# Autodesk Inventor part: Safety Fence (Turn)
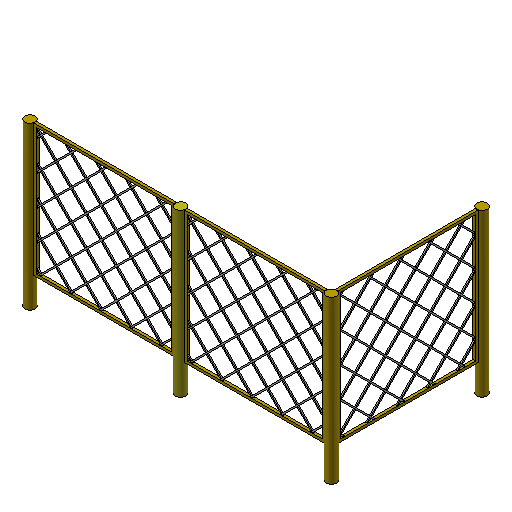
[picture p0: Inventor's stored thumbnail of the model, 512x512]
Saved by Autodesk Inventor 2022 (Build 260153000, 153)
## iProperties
ConnectorClass: SafetyEquipment
family_type: SafetyFence
Created: 2009-11
Part Number: Safety Fence (Turn)
Document SubType Name: Modeling
Designer: Autodesk, Inc.
Density: 1 g/cm^3
Material: 一般
Appearance: 既定
Key Parameters: SectionLength=1321.000 mm;Height=1524.000 mm;BottomHeight=279.000 mm;Number=2.000 ul;Angle=90.00 deg;TurnLength=1321.000 mm;
Author: Autodesk, Inc.
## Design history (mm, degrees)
sketch "Sketch1"
  geometry: L1 (0, -622.5)-(1321, -622.5); L2 (1321, -622.5)-(1321, 622.5); L3 (1321, 622.5)-(0, 622.5); L4 (0, 622.5)-(0, -622.5); L5 (25, -597.5)-(1296, -597.5); L6 (1296, -597.5)-(1296, 597.5); L7 (1296, 597.5)-(25, 597.5); L8 (25, 597.5)-(25, -597.5); 5 further points
  constraints: 16 end point, 4 midpoint, 4 parallel, 2 coincident, 2 horizontal, 2 perpendicular, 1 horizontal alignment, 1 vertical alignment
  dimensions: "d0" = 1245 distance of L3.end L1.start (= Height1); "d2" = 1321 distance of L1.start L1.end (derived); "d53" = 25 distance between parallel lines of L5 L1 (= WidthOfBranch); "d54" = 25 distance between parallel lines of L4 L8 (= WidthOfBranch)
extrude "Extrusion1" new body sketch "Sketch1" stored distance "d4" = 25.4; taper "d5" = 0 deg
sketch "Sketch2"
  geometry: L1 (50.4, 597.5)-(-1448.6, -901.5); L2 (68.361, 597.5)-(-1430.639, -901.5); L3 (-1448.6, -901.5)-(-1430.639, -901.5); L4 (50.4, 597.5)-(68.361, 597.5); L5 (25, 597.5)-(1296, 597.5) reference; L6 (25, -597.5)-(25, 597.5) reference; L7 (1296, 597.5)-(25, 597.5) reference; 2 further points
  constraints: 8 end point, 2 midpoint, 2 parallel, 1 horizontal alignment
  dimensions: "d10" = 12.7 distance between parallel lines of L1 L2; "d20" = 45 deg angle of L5 L1; "d21" = 25.4 distance from line of L6 L1.start; "d51" = 1499 distance between parallel lines of L4 L3 (derived)
extrude "Extrusion2" join sketch "Sketch2" stored distance "d7" = 12.7; taper "d8" = 0 deg
sketch "Sketch3"
  geometry: L1 (-1379.839, 883.539)-(101.2, -597.5); L2 (-1379.839, 901.5)-(119.161, -597.5); L3 (101.2, -597.5)-(119.161, -597.5); L4 (-1379.839, 883.539)-(-1379.839, 901.5); L5 (1296, -597.5)-(25, -597.5) reference; L6 (25, -597.5)-(25, 597.5) reference; 2 further points
  constraints: 8 end point, 2 midpoint, 1 horizontal alignment, 1 parallel, 1 perpendicular
  dimensions: "d13" = 12.7 distance between parallel lines of L1 L2; "d22" = 45 deg angle of L5 L1; "d23" = 76.2 distance of L5.end L1.end; "d24" = 1499 distance from line of L3 L2.start (derived)
extrude "Extrusion3" join sketch "Sketch3" stored distance "d14" = 12.7; taper "d15" = 0 deg
pattern_linear "Rectangular Pattern1" dims "d16" = 113.8 (derived), "d18" = 2845 (derived)
sketch "Sketch4"
  geometry: L1 (25, 597.5)-(25, -597.5) reference; L2 (25, -597.5)-(1296, -597.5) reference; L3 (1296, -597.5)-(1296, 597.5) reference; L4 (1296, 597.5)-(25, 597.5) reference; L5 (1321, -622.5)-(1321, 622.5) reference; L6 (0, -622.5)-(1321, -622.5) reference; L7 (0, 622.5)-(0, -622.5) reference; L8 (1321, 622.5)-(0, 622.5) reference; 1 further point
extrude "Extrusion4" sketch "Sketch4" stored distance "d25" = 127; taper "d26" = 0 deg
pattern_linear "Rectangular Pattern2" dims "d41" = 1420.06 (derived)
sketch "Sketch15"
  geometry: L1 (1194.6, 74.5)-(1176.639, 74.5); L2 (2447.639, 1345.5)-(2465.6, 1345.5); L3 (2465.6, 1345.5)-(1194.6, 74.5); L4 (2447.639, 1345.5)-(1176.639, 74.5); L5 (50.4, 74.5)-(68.361, 74.5); L6 (68.361, 74.5)-(-1202.639, 1345.5); L7 (-1202.639, 1345.5)-(-1220.6, 1345.5); L8 (-1220.6, 1345.5)-(50.4, 74.5); 4 further points
  constraints: 16 end point, 5 parallel, 1 horizontal, 1 horizontal alignment, 1 midpoint
  dimensions: "d87" = 12.7 distance between parallel lines of L3 L4; "d88" = 25.4 distance of point (1220, 74.5) L1.start; "d89" = 1271 horizontal distance of L1.start L2.end (derived); "d90" = 45 deg angle of L1 L4; "d91" = 12.7 distance between parallel lines of L8 L6; "d92" = 25.4 distance of point (25, 74.5) L5.start; "d93" = 1271 horizontal distance of L5.start L7.end (derived); "d94" = 45 deg angle of L6 L5
extrude "Extrusion9" join sketch "Sketch15" stored distance "d97" = 12.7; taper "d98" = 0 deg
sketch "Sketch16"
  geometry: L1 (1370.5, 0)-(49.5, 0) reference; L2 (49.5, 1245)-(1370.5, 1245) reference; L3 (49.5, 0)-(49.5, -3963); L4 (49.5, -3963)-(1370.5, -3963); L5 (1370.5, -3963)-(1370.5, 0); L6 (1370.5, 1245)-(1370.5, 5208); L7 (1370.5, 5208)-(49.5, 5208); L8 (49.5, 5208)-(49.5, 1245)
  constraints: 12 end point, 3 equal length, 3 perpendicular
  dimensions: "d105" = 3963 distance of L4.end L1.start (derived); "d106" = 3963 distance of L2.end L6.end (= d105)
extrude "Extrusion10" cut sketch "Sketch16" distance "d107" = 25.4; taper "d108" = 0 deg
workplane "Work Plane1"
  workaxis "Work Axis1"
workpoint "Work Point1"
  workaxis "Work Axis2"
workaxis "Work Axis3"
workpoint "Work Point2"
workplane "Work Plane5"
  workplane "Work Plane4"
workpoint "Work Point6"
node "Landing Surface"
node "Connector1"
workpoint "Work Point13"
  workaxis "Work Axis9"
  workplane "Work Plane12"
node "Connector2"
workpoint "Work Point14"
node "Insertion Point1"
body "Solid1"
sketch "Sketch9" dims "d42" = 99 (= Diameter)
  geometry: L1 (0, 0)-(0, -25.4) reference; 3 further points
  constraints: 2 horizontal alignment, 1 midpoint, 2 other
extrude "Extrusion5" join sketch "Sketch9" distance "d43" = 1524 (derived); taper "d44" = 0 deg
pattern_linear "Rectangular Pattern3" dims "d114" = 1420.06 (derived)
sketch "Sketch10"
  geometry: L1 (1321, -25.4)-(1321, 0) reference; C1 r 49.5 at (1370.5, -12.7); 1 further point
  constraints: 1 centre point, 1 horizontal alignment, 1 midpoint, 1 tangent
  dimensions: "d45" = 99 diameter of C1 (= Diameter)
extrude "Extrusion6" join sketch "Sketch10" distance "d46" = 1524 (derived); taper "d47" = 0 deg
sketch "Sketch11"
  geometry: L1 (0, -49.5)-(0, 49.5) reference; L2 (0, 49.5)-(0, 1370.5); L3 (0, 1370.5)-(1245, 1370.5); L4 (1245, 1370.5)-(1245, 49.5); L5 (1245, 49.5)-(0, 49.5); L6 (25, 1345.5)-(25, 74.5); L7 (25, 74.5)-(1220, 74.5); L8 (1220, 74.5)-(1220, 1345.5); L9 (1220, 1345.5)-(25, 1345.5); 2 further points
  constraints: 16 end point, 4 parallel, 2 perpendicular, 1 collinear, 3 other
  dimensions: "d59" = 1321 distance of L1.end L2.end (derived); "d60" = 1245 distance of L4.end L1.end (= Height1); "d61" = 25 distance between parallel lines of L2 L6 (= WidthOfBranch)
extrude "Extrusion7" join sketch "Sketch11" stored distance "d62" = 25.4; taper "d63" = 0 deg
extrude "Extrusion8" join sketch "Sketch15" stored distance "d95" = 12.7; taper "d96" = 0 deg
pattern_linear "Rectangular Pattern4" dims "d99" = 113.8 (derived), "d101" = 2845 (derived)
pattern_linear "Rectangular Pattern5" dims "d102" = 113.8 (derived), "d104" = 2845 (derived)
sketch "Sketch17"
  geometry: L1 (0, 1321)-(-25.4, 1321) reference; C1 r 49.5 at (-12.7, 1370.5); 1 further point
  constraints: 1 centre point, 1 tangent
  dimensions: "d109" = 99 diameter of C1 (= Diameter)
extrude "Extrusion11" join sketch "Sketch17" distance "d110" = 1524 (derived); taper "d111" = 0 deg
sketch "Sketch18"
  geometry: C1 r 49.5 at (0, 0) reference; 2 further points
  constraints: 1 coincident
node "Projected Loop1"
feature "Pattern of Solid1:14"
body "Solid15"
other parameters: "WidthOfBranch" = 25 [user parameter; used in 7 equation terms], "Diameter" = 99 [user parameter; used in 3 equation terms], "Height1" = 1245 [user parameter; used in 3 equation terms], "d52" = 90 deg (derived), "d122" = -2840.12 (derived), "d149" = -1519.12, "d150" = 0, "d151" = 0, "d152" = -90 deg, "d153" = 0, "d154" = -180 deg, "d167" = 99 (derived), "d168" = 1370.5, "d169" = 0, "d170" = 1469.5, "d171" = -90 deg, "d172" = 0, "d173" = -90 deg
